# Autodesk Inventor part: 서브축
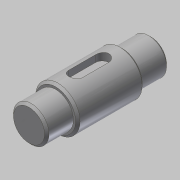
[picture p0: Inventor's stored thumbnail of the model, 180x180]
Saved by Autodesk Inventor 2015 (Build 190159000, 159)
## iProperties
Created: 2019-03
Part Number: 서브축
Material: 강철, 연강
Document SubType Name: Modeling
Designer: mduedu
Density: 1 g/cm^3
Appearance: 강철
Author: mduedu
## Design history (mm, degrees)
sketch "스케치1"
  geometry: L1 (0, 0)-(12, 0); L2 (12, 0)-(12, 8); L3 (12, 8)-(0, 8); L4 (0, 8)-(0, 0); L5 (12, 0)-(42, 0); L6 (42, 0)-(42, 10); L7 (42, 10)-(12, 10); L8 (12, 10)-(12, 0); L9 (42, 0)-(55, 0); L10 (55, 0)-(55, 8); L11 (55, 8)-(42, 8); L12 (42, 8)-(42, 0)
  constraints: 24 end point, 6 parallel, 3 horizontal, 3 perpendicular
  dimensions: "d0" = 16 diameter of L3 L1; "d2" = 20 diameter of L7 L5; "d3" = 16 diameter of L11 L9; "d4" = 12 distance of L2.end L3.end; "d5" = 30 distance of L6.end L7.end; "d6" = 55 distance between parallel lines of L10 L4
revolve "회전1" sketch "스케치1" stored, may be unused: angle "d7" = 90 deg
node "작업 평면1"
sketch "스케치2" dims "d10" = 18
  geometry: L1 (6, -3)-(-6, -3); L2 (-6, -3)-(-6, 3); L3 (-6, 3)-(6, 3); L4 (6, 3)-(6, -3); L5 (15, 10)-(15, -10) reference; 3 further points
  constraints: 8 end point, 2 midpoint, 2 parallel, 2 vertical alignment, 1 horizontal, 1 horizontal alignment, 1 perpendicular, 4 other
  dimensions: "d8" = 6 distance between parallel lines of L3 L1; "d11" = 6 dimension on L5
extrude "돌출1" cut sketch "스케치2" distance "d12" = 3.5; taper "d13" = 0 deg
chamfer "모따기1" distance "d14" = 1; stored, may be unused: second distance "d15" = 2, angle "d16" = 45 deg
chamfer "모따기2" distance "d17" = 1; stored, may be unused: second distance "d18" = 2, angle "d19" = 45 deg
node "솔리드1"
